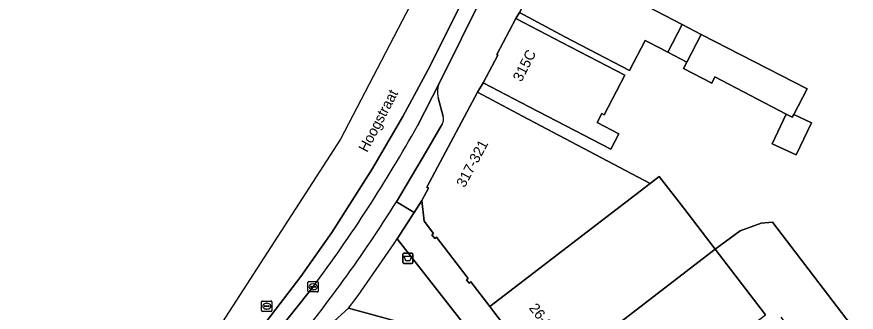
# Model space of a CAD drawing. Extents: x 160157 to 160921, y 381516 to 382045.
# Drawn here: x 160156.6 to 160237.8, y 381644.1 to 381672.6 of the extents above; entities that cross this region are included whole.
import ezdxf

# ---------------------------------------------------------------- set-up
doc = ezdxf.new("R2010")
doc.units = 0
for name, color, linetype in [('IMGEO_Afvalbak', 7, 'Continuous'), ('IMGEO_Erf', 7, 'Continuous'), ('IMGEO_Groenvoorziening', 7, 'Continuous'), ('IMGEO_Haag', 7, 'Continuous'), ('IMGEO_Kolk', 7, 'Continuous'), ('IMGEO_Openbare_ruimte_label', 7, 'Continuous'), ('IMGEO_Pand', 7, 'Continuous'), ('IMGEO_Pand_nummerreeks', 7, 'Continuous'), ('IMGEO_Parkeervlak_open', 7, 'Continuous'), ('IMGEO_Rijbaan_lokaal_gesloten', 7, 'Continuous'), ('IMGEO_Rijbaan_lokaal_open', 7, 'Continuous'), ('IMGEO_Rioolput', 7, 'Continuous'), ('IMGEO_Voetpad_open', 7, 'Continuous')]:
    doc.layers.add(name, color=color, linetype=linetype)

msp = doc.modelspace()

# ---------------------------------------------------------------- linework, layer by layer
at = {"layer": 'IMGEO_Afvalbak'}
for p, q in [((160193.937, 381648.875), (160193.937, 381649.675)), ((160193.937, 381649.675), (160193.937, 381648.875)), ((160194.037, 381649.775), (160194.827, 381649.775)), ((160194.827, 381649.775), (160194.037, 381649.775)), ((160194.927, 381649.675), (160194.927, 381648.875)), ((160194.927, 381648.875), (160194.927, 381649.675)), ((160194.827, 381648.775), (160194.037, 381648.775)), ((160194.037, 381648.775), (160194.827, 381648.775))]:
    msp.add_line(p, q, dxfattribs=at)
msp.add_lwpolyline([(160194.08, 381649.489), (160194.784, 381649.489), (160194.635, 381649.019), (160194.229, 381649.019), (160194.08, 381649.489)], dxfattribs=at)
for centre, start, end in [((160194.037, 381649.675), 90, 180), ((160194.037, 381649.675), 90, 180), ((160194.827, 381649.675), 0, 90), ((160194.827, 381649.675), 360, 90), ((160194.037, 381648.875), 180, 270), ((160194.037, 381648.875), 180, 270), ((160194.827, 381648.875), 270, 0), ((160194.827, 381648.875), 270, 0)]:
    msp.add_arc(centre, 0.1, start, end, dxfattribs=at)
at = {"layer": 'IMGEO_Erf'}
msp.add_lwpolyline([(160216.804, 381674.056), (160220.971, 381671.883), (160222.811, 381670.924), (160233.071, 381665.674), (160231.767, 381663.18), (160233.467, 381662.375), (160231.994, 381659.262), (160229.683, 381660.356), (160231.035, 381663.212), (160224.141, 381666.808), (160223.824, 381666.198), (160221.09, 381667.624), (160221.41, 381668.239), (160219.572, 381669.198), (160217.709, 381670.169), (160217.392, 381670.334), (160215.875, 381667.424), (160209.63, 381670.679), (160205.226, 381673.048), (160204.892, 381672.461), (160209.326, 381670.15), (160215.424, 381666.972), (160213.436, 381663.158), (160213.211, 381663.275), (160212.757, 381662.404), (160214.838, 381661.319), (160214.054, 381659.815), (160206.159, 381663.93), (160201.725, 381666.241), (160201.164, 381665.334), (160205.538, 381663.014), (160217.867, 381656.496), (160218.753, 381657.175), (160221.132, 381654.122), (160224.171, 381650.152), (160226.57, 381651.942), (160228.618, 381652.681), (160229.719, 381652.76), (160246.171, 381631.2)], dxfattribs=at)
at = {"layer": 'IMGEO_Groenvoorziening'}
msp.add_lwpolyline([(160188.705, 381644.442), (160198.267, 381641.825), (160199.175, 381642.535), (160199.769, 381643), (160193.389, 381651.141)], dxfattribs=at)
msp.add_arc((160057.705, 381741.025), 162.755, 323.59946, 326.47736, dxfattribs=at)
at = {"layer": 'IMGEO_Haag'}
msp.add_lwpolyline([(160188.705, 381644.442), (160198.267, 381641.825), (160199.175, 381642.535), (160199.769, 381643), (160193.389, 381651.141)], dxfattribs=at)
msp.add_arc((160057.705, 381741.025), 162.755, 323.59946, 326.47736, dxfattribs=at)
at = {"layer": 'IMGEO_Kolk'}
for p, q in [((160184.767, 381646.085), (160184.767, 381646.937)), ((160184.842, 381647.011), (160185.694, 381647.011)), ((160185.768, 381646.937), (160185.768, 381646.085)), ((160185.026, 381646.505), (160185.026, 381646.517)), ((160185.464, 381646.468), (160185.066, 381646.468)), ((160185.069, 381646.554), (160185.467, 381646.554)), ((160185.278, 381646.231), (160185.253, 381646.231)), ((160185.255, 381646.791), (160185.28, 381646.791)), ((160185.51, 381646.517), (160185.51, 381646.505)), ((160185.694, 381646.011), (160184.842, 381646.011))]:
    msp.add_line(p, q, dxfattribs=at)
for points in [[(160184.767, 381646.085), (160184.767, 381646.937)], [(160184.842, 381647.011), (160185.694, 381647.011)], [(160185.768, 381646.937), (160185.768, 381646.085)], [(160185.694, 381646.011), (160184.842, 381646.011)]]:
    msp.add_lwpolyline(points, dxfattribs=at)
for centre, radius, start, end in [((160184.844, 381646.935), 0.0765, 91.55205, 178.44795), ((160184.844, 381646.935), 0.0765, 91.55205, 178.44795), ((160185.692, 381646.935), 0.0765, 1.55205, 88.44795), ((160185.692, 381646.935), 0.0765, 1.55205, 88.44795), ((160185.066, 381646.514), 0.0403, 85.87752, 175.75265), ((160185.063, 381646.504), 0.0366, 178.93798, 274.71019), ((160185.467, 381646.511), 0.043, 264.86636, 352.45326), ((160185.471, 381646.516), 0.0386, 1.73085, 96.63898), ((160184.844, 381646.087), 0.0765, 181.55205, 268.44795), ((160184.844, 381646.087), 0.0765, 181.55205, 268.44795), ((160185.692, 381646.087), 0.0765, 271.55205, 358.44795), ((160185.692, 381646.087), 0.0765, 271.55205, 358.44795)]:
    msp.add_arc(centre, radius, start, end, dxfattribs=at)
for centre, major_axis, ratio, start_param, end_param in [((160185.254, 381646.511), (-0.387, 0.002), 0.722429, 4.712389, 7.853982), ((160185.279, 381646.511), (-0.39, 0.002), 0.717154, 1.570796, 4.712389)]:
    msp.add_ellipse(centre, major_axis=major_axis, ratio=ratio, start_param=start_param, end_param=end_param, dxfattribs=at)
at = {"layer": 'IMGEO_Pand'}
for points in [[(160216.804, 381674.056), (160208.133, 381678.577), (160205.226, 381673.048), (160209.63, 381670.679), (160215.875, 381667.424), (160217.392, 381670.334), (160217.709, 381670.169), (160219.572, 381669.198), (160220.971, 381671.883)], [(160201.725, 381666.241), (160206.159, 381663.93), (160214.054, 381659.815), (160214.838, 381661.319), (160212.757, 381662.404), (160213.211, 381663.275), (160213.436, 381663.158), (160215.424, 381666.972), (160209.326, 381670.15), (160204.892, 381672.461), (160203.047, 381668.984), (160203.142, 381668.912)], [(160220.971, 381671.883), (160219.572, 381669.198), (160221.41, 381668.239), (160222.811, 381670.924)], [(160222.811, 381670.924), (160221.41, 381668.239), (160221.09, 381667.624), (160223.824, 381666.198), (160224.141, 381666.808), (160231.035, 381663.212), (160231.624, 381662.905), (160231.767, 381663.18), (160233.071, 381665.674)], [(160202.359, 381644.613), (160217.867, 381656.496), (160205.538, 381663.014), (160201.164, 381665.334), (160196.27, 381656.144), (160196.413, 381656.068), (160195.783, 381654.876), (160195.998, 381652.849), (160196.903, 381651.679), (160196.747, 381651.552), (160197.031, 381651.181), (160197.19, 381651.302), (160200.253, 381647.307), (160200.11, 381647.197), (160200.354, 381646.879), (160200.523, 381647.009)], [(160233.467, 381662.375), (160231.767, 381663.18), (160231.624, 381662.905), (160231.035, 381663.212), (160229.683, 381660.356), (160231.994, 381659.262)], [(160207.737, 381637.521), (160212.568, 381631.144), (160229.025, 381643.813), (160224.171, 381650.152)]]:
    msp.add_lwpolyline(points, close=True, dxfattribs=at)
for points in [[(160224.171, 381650.152), (160221.132, 381654.122), (160218.753, 381657.175), (160217.867, 381656.496), (160202.359, 381644.613), (160202.756, 381644.095), (160205.162, 381640.92), (160206.27, 381641.769), (160207.383, 381640.317), (160207.187, 381640.166)], [(160206.994, 381638.502), (160207.737, 381637.521), (160224.171, 381650.152)]]:
    msp.add_lwpolyline(points, dxfattribs=at)
at = {"layer": 'IMGEO_Parkeervlak_open'}
for points in [[(160197.512, 381666.303), (160195.358, 381662.073)], [(160197.863, 381662.969), (160197.361, 381664.786)], [(160193.32, 381654.723), (160196.245, 381659.639), (160197.756, 381662.253)], [(160185.263, 381646.512), (160179.046, 381638.696)]]:
    msp.add_lwpolyline(points, dxfattribs=at)
for centre, radius, start, end in [((160199.429, 381665.346), 2.143, 153.47887, 195.1523), ((160196.986, 381662.734), 0.908, 327.99551, 15.00557), ((160071.591, 381731.31), 141.817, 323.27741, 330.77664), ((160082.645, 381723.888), 130.51, 319.93904, 327.99702)]:
    msp.add_arc(centre, radius, start, end, dxfattribs=at)
at = {"layer": 'IMGEO_Rijbaan_lokaal_gesloten'}
msp.add_lwpolyline([(160156.598, 381625.529), (160157.945, 381624.347), (160157.945, 381624.347), (160166.486, 381629.832), (160169.396, 381631.892), (160170.52, 381632.688), (160172.196, 381634.228), (160176.638, 381638.356), (160180.399, 381642.709), (160184.071, 381647.515), (160187.061, 381651.776), (160191.004, 381657.943), (160193.95, 381662.976), (160196.352, 381667.464), (160199.388, 381673.494), (160206.776, 381688.366), (160215.251, 381705.595), (160217.964, 381710.876), (160214.799, 381712.395), (160214.799, 381712.395), (160192.653, 381669.888), (160187.922, 381660.808), (160171.421, 381635.297)], close=True, dxfattribs=at)
for points in [[(160209.073, 381689.6), (160211.107, 381693.64), (160215.226, 381701.951), (160219.315, 381710.21), (160217.964, 381710.876), (160215.251, 381705.595), (160206.776, 381688.366), (160199.388, 381673.494), (160196.352, 381667.464), (160193.95, 381662.976), (160191.004, 381657.943), (160187.061, 381651.776), (160184.071, 381647.515), (160180.399, 381642.709), (160176.638, 381638.356), (160172.196, 381634.228), (160170.52, 381632.688), (160169.396, 381631.892), (160170.385, 381630.645), (160175.957, 381635.475)], [(160195.358, 381662.073), (160197.512, 381666.303), (160205.85, 381683.09), (160209.073, 381689.6)], [(160178.92, 381638.498), (160179.046, 381638.696), (160185.263, 381646.512)]]:
    msp.add_lwpolyline(points, dxfattribs=at)
msp.add_arc((160071.591, 381731.31), 141.817, 323.27741, 330.77664, dxfattribs=at)
at = {"layer": 'IMGEO_Rijbaan_lokaal_open'}
msp.add_lwpolyline([(160230.499, 381643.584), (160250.004, 381618.161), (160252.688, 381614.66), (160256.595, 381617.668), (160246.171, 381631.2), (160229.719, 381652.76), (160228.618, 381652.681), (160226.57, 381651.942), (160224.171, 381650.152), (160229.025, 381643.813)], dxfattribs=at)
at = {"layer": 'IMGEO_Rioolput'}
for p, q in [((160180.279, 381644.212), (160180.279, 381645.064)), ((160180.354, 381645.138), (160181.206, 381645.138)), ((160180.538, 381644.632), (160180.538, 381644.644)), ((160180.976, 381644.595), (160180.578, 381644.595)), ((160180.581, 381644.681), (160180.979, 381644.681)), ((160180.767, 381644.918), (160180.792, 381644.918)), ((160181.022, 381644.644), (160181.022, 381644.632)), ((160181.28, 381645.064), (160181.28, 381644.212)), ((160181.206, 381644.138), (160180.354, 381644.138)), ((160180.79, 381644.358), (160180.765, 381644.358))]:
    msp.add_line(p, q, dxfattribs=at)
for points in [[(160180.279, 381644.212), (160180.279, 381645.064)], [(160180.354, 381645.138), (160181.206, 381645.138)], [(160181.28, 381645.064), (160181.28, 381644.212)], [(160181.206, 381644.138), (160180.354, 381644.138)]]:
    msp.add_lwpolyline(points, dxfattribs=at)
for centre, radius, start, end in [((160180.356, 381645.062), 0.0765, 91.55205, 178.44795), ((160180.356, 381645.062), 0.0765, 91.55205, 178.44795), ((160180.578, 381644.641), 0.0403, 85.87752, 175.75265), ((160180.575, 381644.631), 0.0366, 178.93798, 274.71019), ((160180.979, 381644.638), 0.043, 264.86636, 352.45326), ((160180.983, 381644.643), 0.0386, 1.73085, 96.63898), ((160181.204, 381645.062), 0.0765, 1.55205, 88.44795), ((160181.204, 381645.062), 0.0765, 1.55205, 88.44795), ((160180.356, 381644.214), 0.0765, 181.55205, 268.44795), ((160180.356, 381644.214), 0.0765, 181.55205, 268.44795), ((160181.204, 381644.214), 0.0765, 271.55205, 358.44795), ((160181.204, 381644.214), 0.0765, 271.55205, 358.44795)]:
    msp.add_arc(centre, radius, start, end, dxfattribs=at)
for centre, major_axis, ratio, start_param, end_param in [((160180.766, 381644.638), (-0.387, 0.002), 0.722429, 4.712389, 7.853982), ((160180.791, 381644.638), (-0.39, 0.002), 0.717154, 1.570796, 4.712389)]:
    msp.add_ellipse(centre, major_axis=major_axis, ratio=ratio, start_param=start_param, end_param=end_param, dxfattribs=at)
at = {"layer": 'IMGEO_Voetpad_open'}
for points in [[(160220.982, 381708.647), (160222.193, 381710.939), (160220.212, 381711.978), (160219.315, 381710.21), (160215.226, 381701.951), (160211.107, 381693.64), (160209.073, 381689.6), (160205.85, 381683.09), (160197.512, 381666.303)], [(160197.756, 381662.253), (160196.245, 381659.639), (160193.32, 381654.723), (160195.029, 381653.713), (160195.783, 381654.876), (160196.413, 381656.068), (160196.27, 381656.144), (160201.164, 381665.334), (160201.725, 381666.241), (160203.142, 381668.912), (160203.047, 381668.984), (160204.892, 381672.461), (160205.226, 381673.048), (160208.133, 381678.577), (160208.219, 381678.741), (160206.165, 381679.813), (160210.988, 381689.03), (160212.452, 381692.053), (160216.514, 381699.956), (160220.982, 381708.647)], [(160197.361, 381664.786), (160197.863, 381662.969)], [(160193.389, 381651.141), (160195.029, 381653.713), (160193.32, 381654.723)], [(160205.162, 381640.92), (160202.756, 381644.095), (160202.359, 381644.613), (160200.523, 381647.009), (160200.354, 381646.879), (160200.11, 381647.197), (160200.253, 381647.307), (160197.19, 381651.302), (160197.031, 381651.181), (160196.747, 381651.552), (160196.903, 381651.679), (160195.998, 381652.849), (160195.783, 381654.876), (160195.029, 381653.713), (160193.389, 381651.141), (160199.769, 381643)], [(160182.267, 381637.368), (160183.151, 381639.11), (160184.101, 381640.301), (160188.705, 381644.442)], [(160198.267, 381641.825), (160188.705, 381644.442), (160184.101, 381640.301)]]:
    msp.add_lwpolyline(points, dxfattribs=at)
for centre, radius, start, end in [((160199.429, 381665.346), 2.143, 153.47887, 195.1523), ((160196.986, 381662.734), 0.908, 327.99551, 15.00557), ((160082.645, 381723.888), 130.51, 319.93904, 327.99702), ((160057.705, 381741.025), 162.755, 323.59946, 326.47736)]:
    msp.add_arc(centre, radius, start, end, dxfattribs=at)

# ---------------------------------------------------------------- texts
at = {"layer": 'IMGEO_Openbare_ruimte_label'}
msp.add_text('Hoogstraat', height=1, rotation=62.48694, dxfattribs=at).set_placement((160190.49, 381659.454))
at = {"layer": 'IMGEO_Pand_nummerreeks'}
for s, rotation, p in [('315C', 63.01644, (160205.419, 381666.266)), ('317-321', 61.96312, (160199.932, 381656.042)), ('26-26C', 307.47123, (160206.108, 381644.444))]:
    msp.add_text(s, height=1, rotation=rotation, dxfattribs=at).set_placement(p)

doc.saveas('drawing.dxf')
